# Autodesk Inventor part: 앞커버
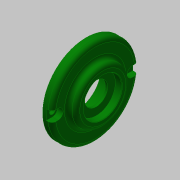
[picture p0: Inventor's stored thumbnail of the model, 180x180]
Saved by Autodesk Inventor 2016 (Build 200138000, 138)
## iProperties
Created: 2019-06
Part Number: 앞커버
Material: 알루미늄 6061
Document SubType Name: Modeling
Designer: mduedu
Density: 1 g/cm^3
Appearance: 진녹색
Author: mduedu
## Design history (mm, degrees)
sketch "스케치1"
  geometry: L1 (0, 0)-(7, 0); L2 (7, 0)-(7, 25); L3 (7, 25)-(0, 25); L4 (0, 25)-(0, 0); L5 (7, 0)-(14, 0); L6 (14, 0)-(14, 34); L7 (14, 34)-(7, 34); L8 (7, 34)-(7, 0); L9 (14, 0)-(20, 0); L10 (20, 0)-(20, 21); L11 (20, 21)-(14, 21); L12 (14, 21)-(14, 0)
  constraints: 24 end point, 6 parallel, 3 horizontal, 3 perpendicular
  dimensions: "d0" = 20 distance between parallel lines of L10 L4; "d2" = 7 distance of L2.end L3.end; "d3" = 7 distance of L6.end L7.end; "d4" = 50 diameter of L3 L1; "d5" = 68 diameter of L7 L5; "d6" = 42 diameter of L11 L9
revolve "회전1" sketch "스케치1" stored, may be unused: angle "d7" = 90 deg
sketch "스케치2"
  geometry: L1 (0, -25)-(0, 25) reference; L2 (0, 25)-(7, 25) reference; L3 (7, 25)-(7, 34) reference; L4 (7, 34)-(14, 34) reference; L5 (14, 34)-(14, 21) reference; L6 (14, 21)-(20, 21) reference; L7 (20, 21)-(20, -21) reference; L8 (20, -21)-(14, -21) reference; L9 (14, -21)-(14, -34) reference; L10 (14, -34)-(7, -34) reference; L11 (7, -34)-(7, -25) reference; L12 (7, -25)-(0, -25) reference; L13 (10, 0)-(10, 17.5); L14 (10, 17.5)-(0, 17.5); L15 (0, 17.5)-(0, 0); L16 (13, 0)-(13, 15); L17 (13, 15)-(10, 15); L18 (10, 15)-(10, 0); L19 (14.8, 0)-(14.8, 9); L20 (14.8, 9)-(13, 9); L21 (13, 9)-(13, 0); L22 (20, 0)-(20, 15); L23 (20, 15)-(14.8, 15); L24 (14.8, 15)-(14.8, 0)
  constraints: 24 end point, 4 horizontal, 4 horizontal alignment, 4 parallel, 4 vertical, 1 point on line, 8 other
  dimensions: "d8" = 35 dimension on L14; "d10" = 30 dimension on L17; "d11" = 18 dimension on L20; "d12" = 30 dimension on L23; "d13" = 10 distance of L13.end L14.end; "d14" = 3 distance of L16.end L17.end; "d15" = 5.2 distance of L22.end L23.end
revolve "회전2" sketch "스케치2" stored, may be unused: angle "d16" = 90 deg
chamfer "모따기1" distance "d18" = 0.5; stored, may be unused: second distance "d19" = 2, angle "d20" = 30 deg
fillet "모깎기2" dims "d21" = 0.3
fillet "모깎기3" dims "d22" = 3
chamfer "모따기2" distance "d23" = 1; stored, may be unused: second distance "d24" = 2, angle "d25" = 30 deg
fillet "모깎기4" dims "d26" = 3
sketch "스케치3" dims "d27" = 58
  geometry: L1 (-4, 29)-(-4, 33.764); L2 (4, 33.764)-(4, 29); A1 r 4 centre (0, 29) between (-4, 29) and (4, 29); A2 r 34 centre (0, 0) between (4, 33.764) and (-4, 33.764); A3 r 34 centre (0, 0) between (4, 33.764) and (-4, 33.764) reference; 3 further points
  constraints: 6 point on circle, 4 end point, 3 coincident, 2 centre point, 2 tangent, 2 vertical, 2 vertical alignment, 1 concentric, 2 other
  dimensions: "d28" = 8 diameter of A1
extrude "돌출1" cut sketch "스케치3" distance "d29" = 4.4; taper "d30" = 0 deg
sketch "스케치4"
  geometry: A1 r 4 centre (0, 29) between (-4, 29) and (4, 29) reference; 2 further points
  constraints: 1 coincident
hole "구멍1" sketch "스케치4" at (0, 29) diameter "d34" = 4.5; stored, may be unused: countersink angle "d38" = 90 deg, drill point angle "d40" = 118 deg; dims "d35" = 6, "d36" = 4, "d37" = 2, "d39" = 8
node "솔리드1"
pattern_circular "원형 패턴1" dims angle "d32" = 360 deg
pattern_circular "원형 패턴2" dims angle "d42" = 360 deg
node "절단 모서리 투영1"
